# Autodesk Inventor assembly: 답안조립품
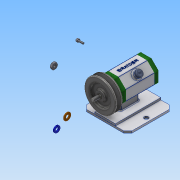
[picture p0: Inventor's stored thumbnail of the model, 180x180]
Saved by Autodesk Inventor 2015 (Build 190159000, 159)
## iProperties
Created: 2018-06
Part Number: 답안조립품
Document SubType Name: Assembly
Designer: SCD-A04
Author: SCD-A04
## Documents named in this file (16)
- C:\Users\SCD-A04\Desktop\480607V1009\답안조립품.iam
- C:\Users\SCD-A04\Desktop\480607V1009\본체.ipt
- C:\Users\SCD-A04\Desktop\480607V1009\앞커버.ipt
- C:\Users\SCD-A04\Desktop\480607V1009\너트 M8.ipt
- 너트 M8.ipt
- C:\Users\SCD-A04\Desktop\480607V1009\키 3x3x12.ipt
- 키 3x3x12.ipt
- C:\Users\SCD-A04\Desktop\480607V1009\볼트 M4x12.ipt
- C:\Users\SCD-A04\Desktop\480607V1009\베어링 15x32x9.ipt
- C:\Users\SCD-A04\Desktop\480607V1009\고무캡.ipt
- C:\Users\SCD-A04\Desktop\480607V1009\뒤커버.ipt
- C:\Users\SCD-A04\Desktop\480607V1009\축.ipt
- C:\Users\SCD-A04\Desktop\480607V1009\스프링와셔 8.ipt
- C:\Users\SCD-A04\Desktop\480607V1009\와셔 8x17.ipt
- C:\Users\SCD-A04\Desktop\480607V1009\V벨트풀리.ipt
- C:\Users\SCD-A04\Desktop\480607V1009\오일 실 15 25 7.ipt
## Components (2 placed, 2 different names)
1. 고무캡:1
2. V벨트풀리:1 — 각도:1
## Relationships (1: Angle 1)
- 각도:1 [Angle]: V벨트풀리:1
